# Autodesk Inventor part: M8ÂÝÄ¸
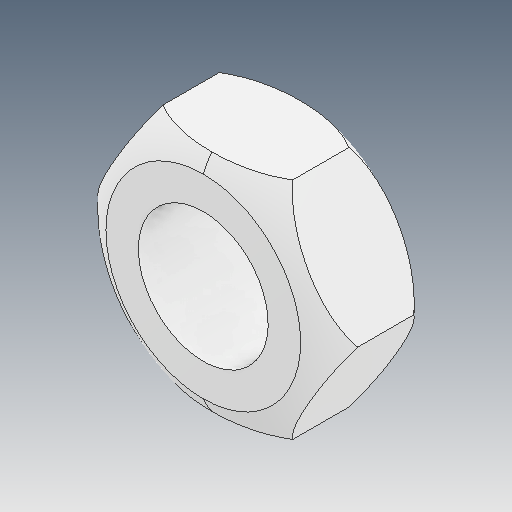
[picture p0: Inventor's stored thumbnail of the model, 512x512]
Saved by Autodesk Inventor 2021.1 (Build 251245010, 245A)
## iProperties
Created: 2021-05
Part Number: M8ÂÝÄ¸
Material: Ogólny
Document SubType Name: Modeling
Designer: user
Density: 1 g/cm^3
Appearance: Domyślna
Author: user
Revision Number: ÈÎºÎ
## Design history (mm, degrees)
feature "ÊäÈë1"
node "Bryła1"
